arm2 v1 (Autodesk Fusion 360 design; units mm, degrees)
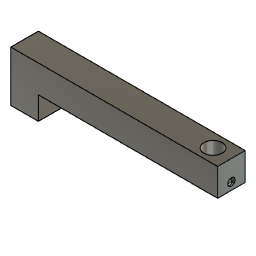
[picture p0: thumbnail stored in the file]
sketch "草图1" plane through (0, 0, 0) normal (0, 0, 1) x axis (1, 0, 0)
  line L1 (-7.5, 7.5) -> (7.5, 7.5)
  line L2 (-7.5, -7.5) -> (-7.5, 7.5)
  line L3 (7.5, -7.5) -> (-7.5, -7.5)
  line L4 (7.5, 7.5) -> (7.5, -7.5)
  line L5 (-7.5, -7.5) -> (7.5, 7.5)
  line L6 (7.5, -7.5) -> (-7.5, 7.5)
  point P6 (0, 0)
  point P1 (0, 0)
  point P4 (-7.5, -7.5)
  point P5 (7.5, -7.5)
  horizontal L1
  perpendicular L1 L2
  parallel L1 L3
  parallel L2 L4
  coincident L5 P6
  coincident L6 P6
  coincident P1 P6
  dimension "d1" distance P4 P5 = 15
  dimension "d2" distance L1 L3 = 15
sketch "草图2" plane through (0, 0, 0) normal (0, 1, 0) x axis (1, 0, 0)
  line L1 (0, -10) -> (0, 0)
  line L2 (87, -20) -> (10, -20)
  line L3 (0, -20) -> (10, -20)
  line L4 (0, -10) -> (0, -20)
  point P1 (0, 0)
  point P2 (0, 0)
  point P3 (0, -20)
  point P7 (0, -20)
  point P4 (87, -20)
  coincident P1 P2
  vertical L1
  perpendicular L1 L2
  coincident P3 L2
  coincident P3 L1
  coincident P3 P7
  dimension "d3" distance P2 P3 = 20
  dimension "d4" distance P3 P4 = 87
sweep "扫掠" sketch "草图1" TwistAngle 0 TaperAngle 0
sketch "草图5" plane through (0, 0, 0) normal (0, 0, -1) x axis (1, 0, 0)
  line L1 (7.5, 7.5) -> (7.5, -7.5)
  line L2 (-7.5, 7.5) -> (7.5, 7.5)
  line L3 (-7.5, -7.5) -> (-7.5, 7.5)
  line L4 (7.5, -7.5) -> (-7.5, -7.5)
  circle C1 centre (0, 0) radius 1.75
  point P1 (0, 0)
  point P10 (0, 0)
  coincident P1 P10
  dimension "d24" diameter C1 = 3.5
extrude "拉伸2" cut sketch "草图5" profile of C1 against normal blind 10
sketch "草图6" plane through (0, 0, 0) normal (0, 0, -1) x axis (1, 0, 0)
  line L1 (7.5, 7.5) -> (7.5, -7.5)
  line L2 (-7.5, 7.5) -> (7.5, 7.5)
  line L3 (-7.5, -7.5) -> (-7.5, 7.5)
  line L4 (7.5, -7.5) -> (-7.5, -7.5)
  line L5 (-6, 4) -> (-3, 4)
  line L6 (-6, -4) -> (-6, 4)
  line L7 (-3, -4) -> (-6, -4)
  line L8 (-3, 4) -> (-3, -4)
  line L9 (-6, -4) -> (-3, 4)
  line L10 (-3, -4) -> (-6, 4)
  circle C1 centre (0, 0) radius 1.75
  point P15 (-4.5, 0)
  point P13 (-6, -4)
  point P14 (-3, -4)
  point P1 (0, 0)
  horizontal L5
  perpendicular L5 L6
  parallel L5 L7
  parallel L6 L8
  coincident L9 P15
  coincident L10 P15
  dimension "d27" distance P13 P14 = 3
  dimension "d28" distance L5 L7 = 8
  dimension "d29" distance P1 P15 = 4.5
extrude "拉伸3" cut sketch "草图6" profile of L5 L6 L7 L8 against normal blind 10
sketch "草图7" plane through (-7.5, 0, 0) normal (-1, 0, 0) x axis (0, -1, 0)
  line L1 (7.5, 0) -> (-7.5, 0)
  line L2 (7.5, 27.5) -> (7.5, 0)
  line L3 (-7.5, 0) -> (-7.5, 27.5)
  line L4 (-7.5, 27.5) -> (7.5, 27.5)
  circle C1 centre (0, 4) radius 2
  point P6 (0, 4)
  dimension "d32" diameter C1 = 4
  dimension "d33" distance L1 P6 = 4
extrude "拉伸4" cut sketch "草图7" profile of C1 against normal blind 7.5
sketch "草图8" plane through (87, 0, 0) normal (1, 0, 0) x axis (0, 1, 0)
  line L1 (7.5, 12.5) -> (-7.5, 12.5)
  line L2 (7.5, 27.5) -> (7.5, 12.5)
  line L3 (-7.5, 27.5) -> (7.5, 27.5)
  line L4 (-7.5, 12.5) -> (-7.5, 27.5)
  line L5 (-7.5, 27.5) -> (7.5, 27.5)
  line L6 (-7.5, 72.5) -> (-7.5, 27.5)
  line L7 (7.5, 72.5) -> (-7.5, 72.5)
  line L8 (7.5, 27.5) -> (7.5, 72.5)
  line L9 (-7.5, 72.5) -> (7.5, 27.5)
  line L10 (7.5, 72.5) -> (-7.5, 27.5)
  point P10 (0, 50)
  point P4 (7.5, 27.5)
  point P6 (7.5, 27.5)
  horizontal L5
  perpendicular L5 L6
  parallel L5 L7
  parallel L6 L8
  coincident L9 P10
  coincident L10 P10
  coincident P4 P6
extrude "拉伸5" add sketch "草图8" profile of L1 L2 L3 L4 L5 L6 L7 L8 along normal blind 10
sketch "草图9" plane through (0, 0, 27.5) normal (0, 0, 1) x axis (-1, 0, 0)
  line L1 (-97, 7.5) -> (7.5, 7.5)
  line L2 (-97, -7.5) -> (-97, 7.5)
  line L3 (7.5, -7.5) -> (-97, -7.5)
  line L4 (7.5, 7.5) -> (7.5, -7.5)
  circle C1 centre (-94.5, -0.04) radius 4
  point P6 (-94.5, -0.04)
  dimension "d59" diameter C1 = 8
  dimension "d60" distance L2 P6 = 2.5
extrude "拉伸7" cut of existing geometry blind -2
extrude "拉伸9" add of existing geometry blind 10
sketch "草图11" plane through (0, 0, 27.5) normal (0, 0, 1) x axis (-1, 0, 0)
  line L1 (7.5, -7.5) -> (-105, -7.5)
  line L2 (7.5, 7.5) -> (7.5, -7.5)
  line L3 (-105, 7.5) -> (7.5, 7.5)
  line L4 (-105, -7.5) -> (-105, 7.5)
  circle C1 centre (-95, 0) radius 5
  dimension "d71" diameter C1 = 10
sketch "草图13" plane through (0, 0, 12.5) normal (0, 0, -1) x axis (1, 0, 0)
  line L1 (7.5, 7.5) -> (105, 7.5)
  line L2 (7.5, -7.5) -> (7.5, 7.5)
  line L3 (105, -7.5) -> (7.5, -7.5)
  line L4 (105, 7.5) -> (105, -7.5)
  line L5 (104, -4) -> (101, -4)
  line L6 (104, 4) -> (104, -4)
  line L7 (101, 4) -> (104, 4)
  line L8 (101, -4) -> (101, 4)
  line L9 (101, 0) -> (101, 0)
  point P10 (101, 0)
  point P6 (101, -4)
  point P7 (104, -4)
  horizontal L5
  vertical L6
  horizontal L7
  vertical L8
  coincident L8 P10
  perpendicular L6 L9
  dimension "d76" distance P6 P7 = 3
  dimension "d77" distance L5 L9 = 4
  dimension "d78" distance L5 L7 = 8
extrude "拉伸10" cut sketch "草图11" profile of C1 against normal blind 27
extrude "拉伸11" cut sketch "草图13" profile of L5 L6 L7 L8 against normal blind 10
sketch "草图14" plane through (105, 0, 0) normal (1, 0, 0) x axis (0, 1, 0)
  line L1 (7.5, 27.5) -> (7.5, 12.5)
  line L2 (-7.5, 27.5) -> (7.5, 27.5)
  line L3 (-7.5, 12.5) -> (-7.5, 27.5)
  line L4 (7.5, 12.5) -> (-7.5, 12.5)
sketch "草图15" plane through (105, 0, 0) normal (1, 0, 0) x axis (0, 1, 0)
  line L1 (7.5, 12.5) -> (-7.5, 12.5)
  circle C1 centre (0, 16.5) radius 2
  point P2 (0, 16.5)
  dimension "d81" diameter C1 = 4
  dimension "d82" distance P2 L1 = 4
extrude "拉伸12" cut sketch "草图15" profile of C1 against normal blind 8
